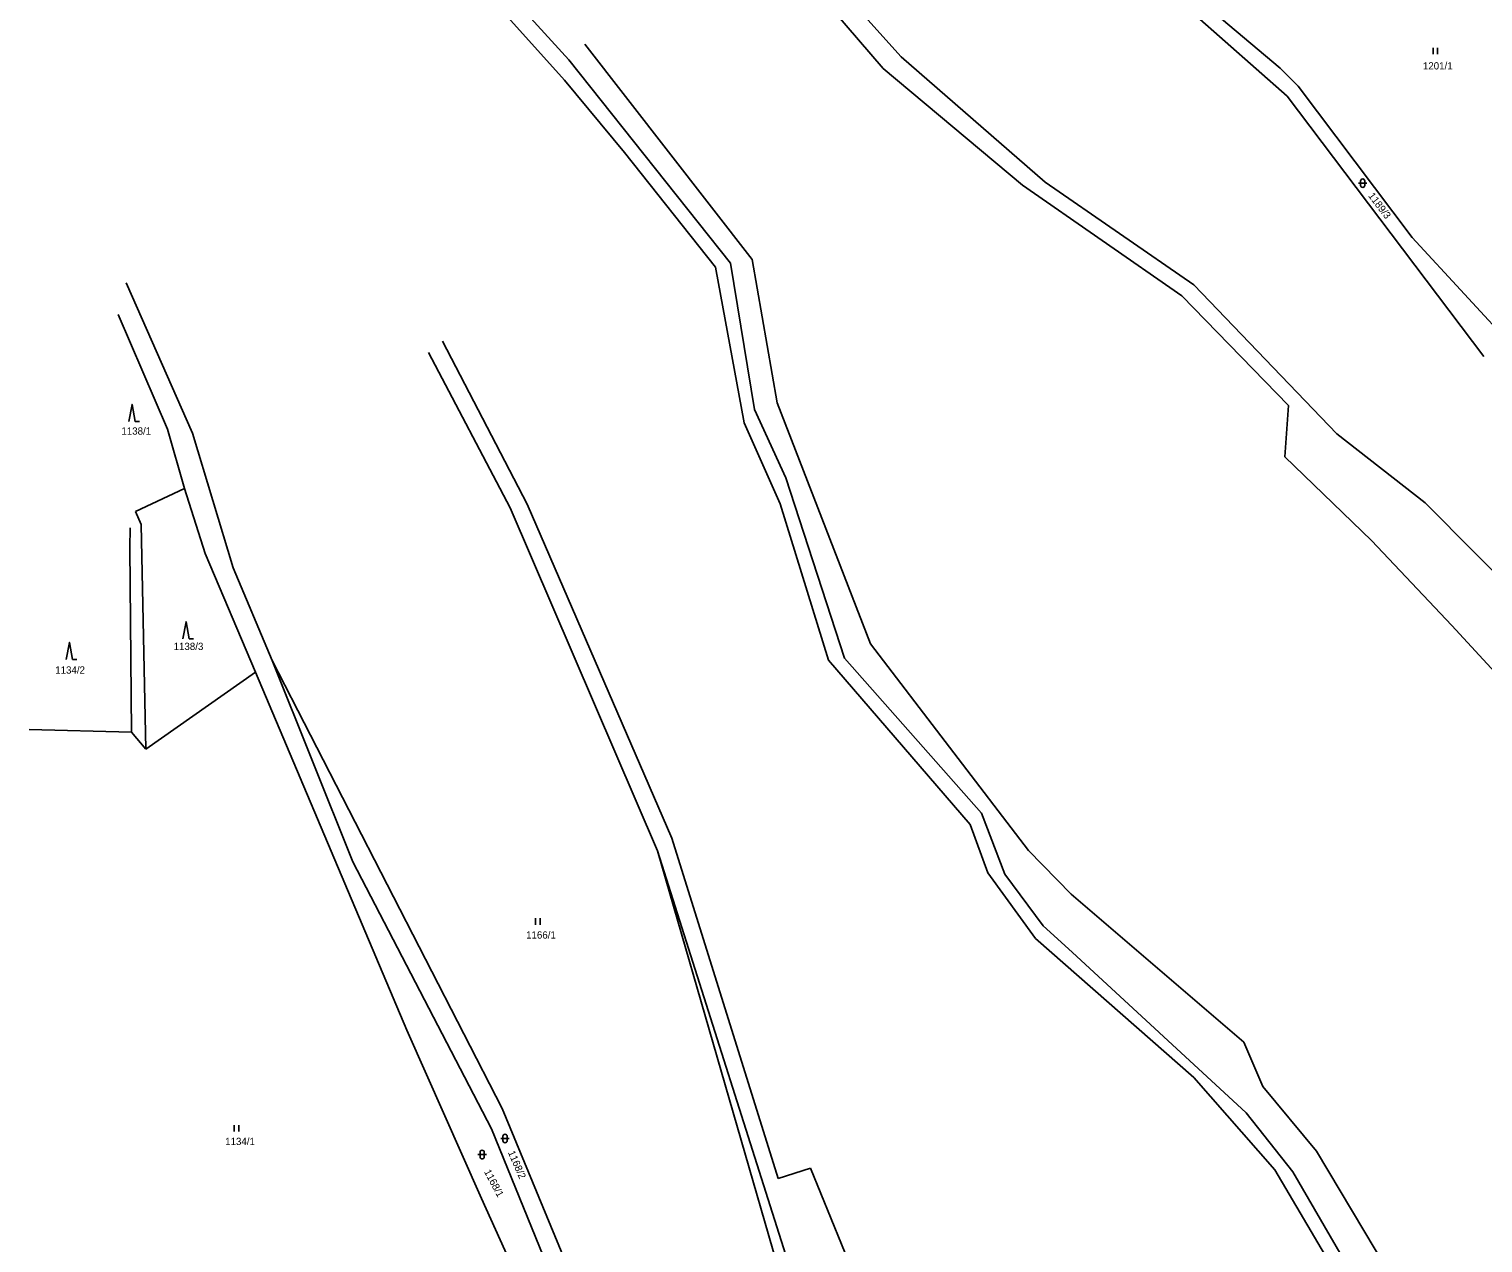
# Model space of a CAD drawing. Extents: x -717507 to -715515, y -957700 to -954941.
# Drawn here: x -717469.3 to -717129.5, y -957227.8 to -956944.1 of the extents above; entities that cross this region are included whole.
import ezdxf

# ---------------------------------------------------------------- set-up
doc = ezdxf.new("R2010")
doc.units = 0
for name, color, linetype in [('Hranice parcel', 7, 'Continuous'), ('Parcelní čísla', 7, 'Continuous'), ('Vnitřní kresba', 7, 'Continuous'), ('Značky kultur', 7, 'Continuous')]:
    doc.layers.add(name, color=color, linetype=linetype)

msp = doc.modelspace()

# ---------------------------------------------------------------- linework, layer by layer
at = {"layer": 'Hranice parcel'}
for points in [[(-717343.19, -956951.26), (-717380.43, -956910.35)], [(-717344.17, -956956.03), (-717381.9, -956914.02)], [(-717205.81, -956928.88), (-717176.91, -956953.25)], [(-717265.49, -956950.61), (-717283.89, -956930.09)], [(-717269.66, -956953.34), (-717286.54, -956933.65)], [(-717175.29, -956959.79), (-717197, -956940.61)], [(-717300.27, -956997.94), (-717339.41, -956947.6)], [(-717305.37, -956998.82), (-717343.19, -956951.26)], [(-717265.49, -956950.61), (-717231.86, -956979.85)], [(-717344.17, -956956.03), (-717330.16, -956972.93)], [(-717237.16, -956980.61), (-717269.66, -956953.34)], [(-717176.91, -956953.25), (-717172.69, -956957.46)], [(-717172.69, -956957.46), (-717146.06, -956992.81)], [(-717175.29, -956959.79), (-717129.34, -957020.62)], [(-717330.16, -956972.93), (-717308.91, -956999.74)], [(-717197.1, -957003.86), (-717231.86, -956979.85)], [(-717199.9, -957006.44), (-717237.16, -956980.61)], [(-717121.57, -957019.32), (-717146.06, -956992.81)], [(-717308.91, -956999.74), (-717302.16, -957036.17)], [(-717305.37, -956998.82), (-717299.78, -957032.99)], [(-717300.27, -956997.94), (-717294.46, -957031.46)], [(-717431.09, -957038.51), (-717446.6, -957003.41)], [(-717197.1, -957003.86), (-717163.64, -957038.74)], [(-717174.98, -957032.11), (-717199.9, -957006.44)], [(-717448.5, -957010.81), (-717436.96, -957037.64)], [(-717372.7, -957017.05), (-717352.86, -957055.15)], [(-717356.88, -957056), (-717375.93, -957019.68)], [(-717299.78, -957032.99), (-717292.45, -957048.98)], [(-717294.46, -957031.46), (-717272.67, -957087.82)], [(-717174.98, -957032.11), (-717175.81, -957044.09)], [(-717432.94, -957051.5), (-717436.96, -957037.64)], [(-717302.16, -957036.17), (-717293.77, -957055.09)], [(-717431.09, -957038.51), (-717421.58, -957070.05)], [(-717163.64, -957038.74), (-717143.05, -957054.83)], [(-717175.81, -957044.09), (-717155.59, -957063.64)], [(-717444.41, -957056.87), (-717432.94, -957051.5)], [(-717428.14, -957066.7), (-717432.94, -957051.5)], [(-717278.71, -957091.12), (-717292.45, -957048.98)], [(-717119.57, -957078.45), (-717143.05, -957054.83)], [(-717443.13, -957059.93), (-717444.41, -957056.87)], [(-717322.46, -957136.19), (-717356.88, -957056)], [(-717352.86, -957055.15), (-717319.1, -957133.24)], [(-717282.5, -957091.61), (-717293.77, -957055.09)], [(-717445.69, -957060.66), (-717445.76, -957065.38)], [(-717442.04, -957112.43), (-717443.13, -957059.93)], [(-717155.59, -957063.64), (-717136.81, -957083.48)], [(-717445.76, -957065.38), (-717445.39, -957108.46)], [(-717428.14, -957066.7), (-717416.36, -957094.38)], [(-717421.58, -957070.05), (-717412.49, -957091.67)], [(-717136.81, -957083.48), (-717113.86, -957108.34)], [(-717272.67, -957087.82), (-717235.75, -957136.11)], [(-717412.49, -957091.67), (-717393.62, -957138.72)], [(-717358.76, -957196.42), (-717412.49, -957091.67)], [(-717282.5, -957091.61), (-717249.36, -957130.02)], [(-717246.67, -957127.4), (-717278.71, -957091.12)], [(-717416.36, -957094.38), (-717442.04, -957112.43)], [(-717416.36, -957094.38), (-717381.04, -957178.06)], [(-717469.3, -957107.84), (-717445.39, -957108.46)], [(-717445.39, -957108.46), (-717442.04, -957112.43)], [(-717241.24, -957141.62), (-717246.67, -957127.4)], [(-717245.21, -957141.32), (-717249.36, -957130.02)], [(-717322.46, -957136.19), (-717288.83, -957241.99)], [(-717319.1, -957133.24), (-717294.26, -957212.74)], [(-717225.73, -957146.32), (-717235.75, -957136.11)], [(-717361.22, -957201.13), (-717393.62, -957138.72)], [(-717245.21, -957141.32), (-717234.09, -957156.64)], [(-717241.24, -957141.62), (-717232.32, -957153.71)], [(-717185.41, -957180.88), (-717225.73, -957146.32)], [(-717197.1, -957189.13), (-717234.09, -957156.64)], [(-717225.55, -957159.88), (-717232.32, -957153.71)], [(-717184.89, -957197.43), (-717225.55, -957159.88)], [(-717381.04, -957178.06), (-717363.58, -957217.39)], [(-717180.98, -957191.26), (-717185.41, -957180.88)], [(-717178.17, -957210.74), (-717197.1, -957189.13)], [(-717168.4, -957206.34), (-717180.98, -957191.26)], [(-717358.76, -957196.42), (-717336.91, -957249.12)], [(-717173.96, -957211.17), (-717184.89, -957197.43)], [(-717337.93, -957258.37), (-717361.22, -957201.13)], [(-717129.7, -957271.27), (-717168.4, -957206.34)], [(-717294.26, -957212.74), (-717286.69, -957210.36)], [(-717286.69, -957210.36), (-717260.14, -957275.45)], [(-717149.6, -957259.26), (-717178.17, -957210.74)], [(-717146.37, -957258.71), (-717173.96, -957211.17)], [(-717363.58, -957217.39), (-717333.07, -957284.89)]]:
    msp.add_lwpolyline(points, dxfattribs=at)
at = {"layer": 'Vnitřní kresba'}
msp.add_lwpolyline([(-717322.46, -957136.19), (-717290.82, -957245.58)], dxfattribs=at)
at = {"layer": 'Značky kultur'}
for points in [[(-717141.17, -956949.99), (-717141.17, -956948.49)], [(-717140.13, -956949.99), (-717140.13, -956948.49)], [(-717158.62, -956980.13), (-717156.62, -956980.13)], [(-717158.12, -956980.63), (-717158.12, -956979.63)], [(-717157.12, -956979.63), (-717157.12, -956980.63)], [(-717445.98, -957035.84), (-717445.23, -957031.84), (-717444.48, -957035.84), (-717443.48, -957035.84)], [(-717433.37, -957086.61), (-717432.62, -957082.61), (-717431.87, -957086.61), (-717430.87, -957086.61)], [(-717460.62, -957091.44), (-717459.87, -957087.44), (-717459.12, -957091.44), (-717458.12, -957091.44)], [(-717350.91, -957153.43), (-717350.91, -957151.93)], [(-717349.87, -957153.43), (-717349.87, -957151.93)], [(-717421.34, -957201.8), (-717421.34, -957200.3)], [(-717420.3, -957201.8), (-717420.3, -957200.3)], [(-717359.06, -957203.39), (-717357.06, -957203.39)], [(-717358.56, -957203.89), (-717358.56, -957202.89)], [(-717357.56, -957202.89), (-717357.56, -957203.89)], [(-717364.41, -957207.16), (-717362.41, -957207.16)], [(-717363.91, -957207.66), (-717363.91, -957206.66)], [(-717362.91, -957206.66), (-717362.91, -957207.66)]]:
    msp.add_lwpolyline(points, dxfattribs=at)
for centre, start, end in [((-717157.62, -956979.63), 0.101, 180.0014), ((-717157.62, -956980.63), 180.1024, 0.0029), ((-717358.06, -957202.89), 0.101, 180.0014), ((-717358.06, -957203.89), 180.1024, 0.0029), ((-717363.41, -957206.66), 0.101, 180.0014), ((-717363.41, -957207.66), 180.1024, 0.0029)]:
    msp.add_arc(centre, 0.5, start, end, dxfattribs=at)

# ---------------------------------------------------------------- texts
at = {"layer": 'Parcelní čísla'}
for s, p in [('1201/1', (-717143.55, -956953.55)), ('1138/1', (-717447.72, -957038.9)), ('1138/3', (-717435.52, -957089.23)), ('1134/2', (-717463.19, -957094.76)), ('1166/1', (-717353.14, -957156.68)), ('1134/1', (-717423.47, -957204.93))]:
    msp.add_text(s, height=1.7, dxfattribs=at).set_placement(p)
for s, rotation, p in [('1189/3', 307.1024, (-717156.42, -956983.09)), ('1168/2', 293.4023, (-717357.42, -957206.64)), ('1168/1', 298.0024, (-717363.02, -957211.16))]:
    msp.add_text(s, height=1.7, rotation=rotation, dxfattribs=at).set_placement(p)

doc.saveas('drawing.dxf')
